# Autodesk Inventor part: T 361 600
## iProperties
Company: Mayer & Müller AG Schaltgeräte
Created: 2006-10
Part Number: T 361 600
Material: 2.0321.10
Document SubType Name: Modeling
Designer: I.Baliuc
Manufacturer: Standard
Standards Organization: Custom
Description: Gewindeplatte
Density: 8.2 g/cm^3
HalbzeugNorm: DIN 1759
Zweck: für Vorkontaktbefestigung
Abmessung: 30 x 5 - 20
Author: T.Messerschmitt
Keywords: 382057
Revision Number: 361600
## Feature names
1. Extrusion2
2. Bohrung_M6 [Hole]
